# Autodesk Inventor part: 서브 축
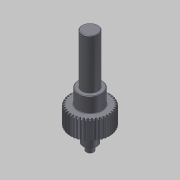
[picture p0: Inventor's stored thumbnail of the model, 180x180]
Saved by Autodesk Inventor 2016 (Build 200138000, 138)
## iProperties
Created: 2016-02
Part Number: 서브 축
Material: 강철, 연강
Document SubType Name: Modeling
Designer: mdu
Categories: <?xml version="1.0" encoding="UTF-16"?> <MemberInstance><Categories><FamilyTemplate><FamilyTemplateParameter ValueType="xs:double" Id="1" ObjectReferenceKey="da
Density: 7.86 g/cm^3
Appearance: 강철
CustomPartVersion: 1
Author: mdu
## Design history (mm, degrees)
sketch "Sketch1"
  geometry: C1 r 21 at (0, 0)
  constraints: 1 centre point
  dimensions: "d0" = 42 diameter of C1 (= da_da)
extrude "Extrusion1" new body sketch "Sketch1" distance "d1" = 20 (= da_b); taper "d2" = 0 deg
workplane "Work Plane2"
feature "피치 지름" dims "d4" = 10, "d5" = 0
workplane "Work Plane8"
workplane "Work Plane9"
chamfer "모따기1" distance "d49" = 1; stored, may be unused: second distance "d50" = 2, angle "d51" = 45 deg
sketch "스케치3"
  geometry: C1 r 12.5 at (0, 0); 1 further point
  constraints: 1 centre point, 1 coincident
  dimensions: "d52" = 25 diameter of C1
extrude "돌출2" join sketch "스케치3" distance "d53" = 16; taper "d54" = 0 deg
sketch "스케치4"
  geometry: C1 r 8.5 at (0, 0); 1 further point
  constraints: 1 centre point, 1 coincident
  dimensions: "d55" = 17 diameter of C1
extrude "돌출3" join sketch "스케치4" distance "d56" = 53; taper "d57" = 0 deg
sketch "스케치5"
  geometry: C1 r 7.5 at (0, 0); 1 further point
  constraints: 1 centre point, 1 coincident
  dimensions: "d62" = 15 diameter of C1
extrude "돌출4" join sketch "스케치5" distance "d63" = 16; taper "d64" = 0 deg
sketch "스케치6"
  geometry: C1 r 4 at (0, 0); 1 further point
  constraints: 1 centre point, 1 coincident
  dimensions: "d65" = 8 diameter of C1
extrude "돌출5" join sketch "스케치6" distance "d66" = 7; taper "d67" = 0 deg
chamfer "모따기2" distance "d58" = 0.5; stored, may be unused: second distance "d59" = 2, angle "d60" = 45 deg
fillet "모깎기1" dims "d61" = 0.5
feature "스퍼 기어" dims "da_b" = 20, "da_d" = 40, "da_aw" = 31, "da_da" = 42, "da_df" = 37.5, "da_dw" = 40, angle "da_beta" = 0 deg, "da_lefttooth" = 0, "da_righttooth" = 0
body "Solid1"
sketch "Sketch2"
  geometry: C1 r 21 at (0, 0) reference; C2 r 20 at (0, 0)
  constraints: 1 centre point, 1 coincident
  dimensions: "d3" = 40 diameter of C2 (= da_dw)
body "Srf1"
other parameters: "d16" = 31 (= da_aw), "d17" = 0, "d34" = 4.5 deg (computed from da_z), "d39" = 0, "d41" = 0, "d43" = 31 (= da_aw), "d46" = 31 (= da_aw), "d47" = 0, "d48" = 0
